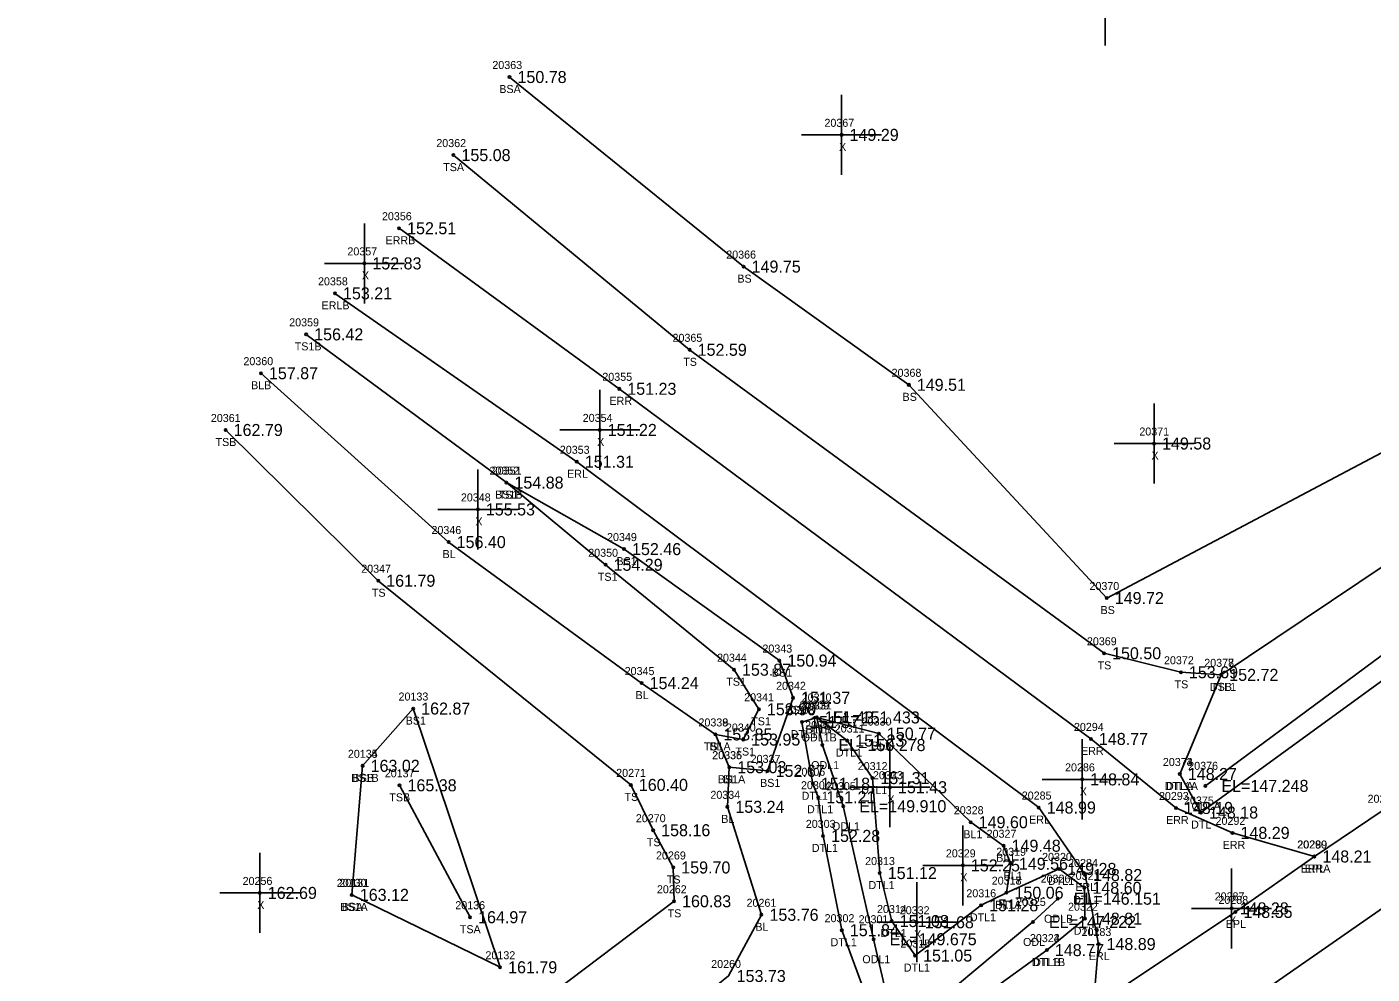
# Model space of a CAD drawing. Extents: x 2449605 to 2452431, y 1012876 to 1014922.
# Drawn here: x 2450467.1 to 2450635.2, y 1013641.9 to 1013760.1 of the extents above; entities that cross this region are included whole.
import ezdxf

# ---------------------------------------------------------------- set-up
doc = ezdxf.new("R2010")
doc.units = 0
for name, color, linetype in [('RD_DTM_BkLn1', 7, 'Continuous'), ('RD_DTM_BkLn2', 7, 'Continuous'), ('RD_DTM_BkLn_txCode', 7, 'Continuous'), ('RD_EX_H2O', 7, 'Continuous'), ('RD_EX_H2O_txCode', 7, 'Continuous'), ('RD_EX_Misc', 7, 'Continuous'), ('RD_EX_Misc_txCode', 7, 'Continuous'), ('RD_EX_Road', 7, 'Continuous'), ('RD_EX_Road_txCode', 7, 'Continuous'), ('RD_EX_TX_H2O_ELEV', 7, 'Continuous'), ('RD_EX_TX_Misc_ELEV', 7, 'Continuous'), ('RD_EX_TX_Road_ELEV', 7, 'Continuous'), ('RD_SMD_Locator', 7, 'Continuous')]:
    doc.layers.add(name, color=color, linetype=linetype)

msp = doc.modelspace()

# ---------------------------------------------------------------- linework, layer by layer
at = {"layer": 'RD_DTM_BkLn1'}
for points in [[(2449680.58, 1012985.87), (2449759.39, 1013040.31), (2449841.07, 1013097.15), (2449921.06, 1013152.87), (2450001.23, 1013208.89), (2450080.46, 1013264.17), (2450161.02, 1013320.22), (2450242.03, 1013376.29), (2450324.02, 1013432.88), (2450405.2, 1013489.3), (2450483.11, 1013543.86), (2450561.65, 1013598.14), (2450642.32, 1013654.18), (2450739.61, 1013721.61), (2450817.44, 1013775.86), (2450896.72, 1013831.42), (2450912.5, 1013842.34)], [(2450327.03, 1013465.64), (2450385.25, 1013515.48), (2450463.3, 1013570.54), (2450494.41, 1013598.14), (2450510.44, 1013608.45), (2450522.79, 1013616.8), (2450540.89, 1013630.45), (2450554.77, 1013641.65), (2450558.87, 1013649.29), (2450554.61, 1013662.77), (2450554.85, 1013667.72), (2450553.11, 1013671.81), (2450543.9, 1013678.22), (2450519.79, 1013695.83), (2450496.34, 1013716.91)], [(2450589.48, 1013652.05), (2450590.03, 1013655.66), (2450589.12, 1013657.91), (2450585.01, 1013660.85), (2450573.54, 1013671.92), (2450565.77, 1013673.93)]]:
    msp.add_lwpolyline(points, dxfattribs=at)
at = {"layer": 'RD_DTM_BkLn2'}
for p, q in [((2450507.69, 1013651.78), (2450509.04, 1013667.89)), ((2450522.47, 1013648.99), (2450513.65, 1013665.46))]:
    msp.add_line(p, q, dxfattribs=at)
for points in [[(2450527.39, 1013753.89), (2450556.64, 1013730.22), (2450577.28, 1013715.46), (2450602.01, 1013688.84), (2450690.63, 1013735.67), (2450719.37, 1013748.33)], [(2450520.39, 1013744.14), (2450549.9, 1013719.83), (2450601.67, 1013681.94), (2450611.27, 1013679.57), (2450616.31, 1013679.25)], [(2450553.11, 1013671.81), (2450556.59, 1013671.17), (2450558.55, 1013674.95), (2450555.44, 1013679.89), (2450539.39, 1013692.99), (2450527.01, 1013703.25), (2450501.99, 1013721.76)], [(2450301.63, 1013463.11), (2450375.81, 1013524.05), (2450456.92, 1013583.6), (2450494.97, 1013610.67), (2450491.89, 1013618.21), (2450482.67, 1013624.66), (2450481.76, 1013627.8), (2450488.9, 1013631.4), (2450492.06, 1013631.7), (2450504.7, 1013625.87), (2450511.15, 1013621.59), (2450516.87, 1013625.3), (2450533.14, 1013639.8), (2450547.95, 1013650.98), (2450547.85, 1013655.2), (2450545.34, 1013659.85), (2450542.55, 1013665.51), (2450510.99, 1013691), (2450491.93, 1013709.82)], [(2450554.85, 1013667.72), (2450559.64, 1013667.26), (2450562.82, 1013676.38), (2450561.11, 1013681.03), (2450541.7, 1013694.95), (2450527.01, 1013703.25)], [(2450507.69, 1013651.78), (2450526.22, 1013642.74), (2450515.36, 1013675.04), (2450509.04, 1013667.89)]]:
    msp.add_lwpolyline(points, dxfattribs=at)
at = {"layer": 'RD_EX_H2O'}
for points in [[(2450611.14, 1013666.87), (2450616.31, 1013679.25), (2450719.37, 1013748.33), (2450722.94, 1013749.68), (2450728.13, 1013757.45), (2450733.94, 1013756.08)], [(2450611.14, 1013666.87), (2450613.78, 1013662.06), (2450716.62, 1013736.81), (2450727.45, 1013740.5), (2450727.63, 1013739.78), (2450734.85, 1013745.44), (2450737.25, 1013753.64), (2450733.94, 1013756.08)], [(2450614.33, 1013665.39), (2450714.94, 1013739.79), (2450717.62, 1013740.69), (2450725.97, 1013743.31), (2450729.59, 1013752.89)], [(2450572.09, 1013638.8), (2450568.91, 1013647.37), (2450566.57, 1013659.14), (2450565.97, 1013663.97), (2450565.3, 1013665.65), (2450563.93, 1013673.35), (2450565.77, 1013673.93), (2450569.58, 1013671.05), (2450572.73, 1013666.36), (2450573.65, 1013654.5), (2450575.14, 1013648.51), (2450578.06, 1013644.2), (2450586.32, 1013650.48), (2450589.48, 1013652.05), (2450596.08, 1013655.02), (2450599.22, 1013652.66), (2450599.29, 1013648.8), (2450594.53, 1013644.88)], [(2450576.23, 1013634.6), (2450574.68, 1013638.41), (2450572.88, 1013646.24), (2450569.09, 1013662.85), (2450566.49, 1013670.48), (2450565.77, 1013673.93)], [(2450086.85, 1013301.88), (2450146.88, 1013340.5), (2450228.43, 1013395.92), (2450309.72, 1013451.69), (2450392.54, 1013506.78), (2450470.72, 1013561.36), (2450549.83, 1013616.71), (2450576.23, 1013634.6), (2450592.79, 1013648.4), (2450595.89, 1013651.3)], [(2450082.81, 1013302.86), (2450086.85, 1013297.03), (2450148.02, 1013337.87), (2450230.55, 1013392.65), (2450311.52, 1013448.88), (2450394.54, 1013504.43), (2450473.16, 1013557.42), (2450552.01, 1013612.78), (2450577.68, 1013632.73), (2450594.53, 1013644.88)]]:
    msp.add_lwpolyline(points, dxfattribs=at)
at = {"layer": 'RD_EX_Misc'}
for p, q in [((2450601.83, 1013757.82), (2450601.83, 1013767.82)), ((2450568.88, 1013741.67), (2450568.88, 1013751.67)), ((2450563.88, 1013746.67), (2450573.88, 1013746.67)), ((2450509.26, 1013725.62), (2450509.26, 1013735.62)), ((2450504.26, 1013730.62), (2450514.26, 1013730.62)), ((2450538.66, 1013704.83), (2450538.66, 1013714.83)), ((2450607.92, 1013703.13), (2450607.92, 1013713.13)), ((2450533.66, 1013709.83), (2450543.66, 1013709.83)), ((2450602.92, 1013708.13), (2450612.92, 1013708.13)), ((2450523.44, 1013694.9), (2450523.44, 1013704.9)), ((2450518.44, 1013699.9), (2450528.44, 1013699.9)), ((2450598.94, 1013661.2), (2450598.94, 1013671.2)), ((2450574.92, 1013660.22), (2450574.92, 1013670.22)), ((2450593.94, 1013666.2), (2450603.94, 1013666.2)), ((2450569.92, 1013665.22), (2450579.92, 1013665.22)), ((2450584.03, 1013650.46), (2450584.03, 1013660.46)), ((2450496.19, 1013647.02), (2450496.19, 1013657.02)), ((2450579.03, 1013655.46), (2450589.03, 1013655.46)), ((2450617.61, 1013645.09), (2450617.61, 1013655.09)), ((2450578.27, 1013643.36), (2450578.27, 1013653.36)), ((2450491.19, 1013652.02), (2450501.19, 1013652.02)), ((2450612.61, 1013650.09), (2450622.61, 1013650.09)), ((2450573.27, 1013648.36), (2450583.27, 1013648.36))]:
    msp.add_line(p, q, dxfattribs=at)
at = {"layer": 'RD_EX_Road'}
for points in [[(2449674.89, 1012994.69), (2449752.35, 1013048.28), (2449834.92, 1013105.96), (2449914.72, 1013161.11), (2449995.66, 1013217.59), (2450075.29, 1013272.9), (2450081.34, 1013277.24), (2450093.41, 1013285.64), (2450155.49, 1013328.69), (2450236.05, 1013384.7), (2450317.88, 1013441.24), (2450398.87, 1013497.28), (2450477.09, 1013551.76), (2450555.6, 1013606.73), (2450600.18, 1013637.7), (2450618.08, 1013649.65), (2450627.95, 1013656.57), (2450636.43, 1013662.28), (2450733.79, 1013730.39), (2450811.43, 1013784.18), (2450891.39, 1013839.9), (2450907.04, 1013850.14)], [(2450627.95, 1013656.57), (2450617.72, 1013659.52), (2450610.65, 1013662.63), (2450600.03, 1013671.25), (2450541.11, 1013714.96), (2450513.6, 1013735.01)], [(2450600.18, 1013637.7), (2450600.45, 1013639.09), (2450600.98, 1013645.64), (2450599.3, 1013654.26), (2450593.51, 1013662.68), (2450535.8, 1013705.85), (2450505.59, 1013726.88)]]:
    msp.add_lwpolyline(points, dxfattribs=at)
at = {"layer": 'RD_SMD_Locator'}
for centre in [(2450527.39, 1013753.89), (2450568.88, 1013746.67), (2450520.39, 1013744.14), (2450513.6, 1013735.01), (2450509.26, 1013730.62), (2450556.64, 1013730.22), (2450505.59, 1013726.88), (2450501.99, 1013721.76), (2450549.9, 1013719.83), (2450496.34, 1013716.91), (2450541.11, 1013714.96), (2450577.28, 1013715.46), (2450491.93, 1013709.82), (2450538.66, 1013709.83), (2450607.92, 1013708.13), (2450535.8, 1013705.85), (2450527.01, 1013703.25), (2450527.01, 1013703.25), (2450523.44, 1013699.9), (2450519.79, 1013695.83), (2450541.7, 1013694.95), (2450539.39, 1013692.99), (2450510.99, 1013691), (2450602.01, 1013688.84), (2450561.11, 1013681.03), (2450601.67, 1013681.94), (2450555.44, 1013679.89), (2450611.27, 1013679.57), (2450616.31, 1013679.25), (2450616.31, 1013679.25), (2450543.9, 1013678.22), (2450562.82, 1013676.38), (2450515.36, 1013675.04), (2450558.55, 1013674.95), (2450563.93, 1013673.35), (2450565.77, 1013673.93), (2450565.77, 1013673.93), (2450565.77, 1013673.93), (2450553.11, 1013671.81), (2450553.11, 1013671.81), (2450556.59, 1013671.17), (2450569.58, 1013671.05), (2450573.54, 1013671.92), (2450600.03, 1013671.25), (2450566.49, 1013670.48), (2450509.04, 1013667.89), (2450509.04, 1013667.89), (2450554.85, 1013667.72), (2450554.85, 1013667.72), (2450559.64, 1013667.26), (2450565.3, 1013665.65), (2450572.73, 1013666.36), (2450598.94, 1013666.2), (2450611.14, 1013666.87), (2450611.14, 1013666.87), (2450513.65, 1013665.46), (2450542.55, 1013665.51), (2450565.97, 1013663.97), (2450574.92, 1013665.22), (2450614.33, 1013665.39), (2450554.61, 1013662.77), (2450569.09, 1013662.85), (2450593.51, 1013662.68), (2450610.65, 1013662.63), (2450585.01, 1013660.85), (2450613.78, 1013662.06), (2450545.34, 1013659.85), (2450566.57, 1013659.14), (2450617.72, 1013659.52), (2450589.12, 1013657.91), (2450590.03, 1013655.66), (2450627.95, 1013656.57), (2450627.95, 1013656.57), (2450547.85, 1013655.2), (2450573.65, 1013654.5), (2450584.03, 1013655.46), (2450596.08, 1013655.02), (2450599.3, 1013654.26), (2450599.22, 1013652.66), (2450496.19, 1013652.02), (2450507.69, 1013651.78), (2450507.69, 1013651.78), (2450547.95, 1013650.98), (2450586.32, 1013650.48), (2450589.48, 1013652.05), (2450589.48, 1013652.05), (2450595.89, 1013651.3), (2450522.47, 1013648.99), (2450558.87, 1013649.29), (2450599.29, 1013648.8), (2450617.61, 1013650.09), (2450618.08, 1013649.65), (2450568.91, 1013647.37), (2450575.14, 1013648.51), (2450578.27, 1013648.36), (2450592.79, 1013648.4), (2450572.88, 1013646.24), (2450600.98, 1013645.64), (2450578.06, 1013644.2), (2450594.53, 1013644.88), (2450594.53, 1013644.88), (2450526.22, 1013642.74)]:
    msp.add_circle(centre, 0.15, dxfattribs=at)

# ---------------------------------------------------------------- texts
at = {"layer": 'RD_DTM_BkLn_txCode'}
for s, p in [('20363', (2450525.25, 1013754.89)), ('BSA', (2450526.12, 1013751.89)), ('20362', (2450518.25, 1013745.14)), ('TSA', (2450519.11, 1013742.14)), ('20366', (2450554.47, 1013731.22)), ('BS', (2450555.86, 1013728.22)), ('20359', (2450499.87, 1013722.76)), ('20365', (2450547.76, 1013720.83)), ('TS1B', (2450500.56, 1013719.76)), ('20360', (2450494.15, 1013717.91)), ('TS', (2450549.1, 1013717.83)), ('20368', (2450575.13, 1013716.46)), ('BLB', (2450495.11, 1013714.91)), ('BS', (2450576.5, 1013713.46)), ('20361', (2450490.08, 1013710.82)), ('TSB', (2450490.67, 1013707.82)), ('20352', (2450524.89, 1013704.25)), ('20351', (2450525.18, 1013704.25)), ('BS1B', (2450525.59, 1013701.25)), ('TS1', (2450526.05, 1013701.25)), ('20346', (2450517.64, 1013696.83)), ('20349', (2450539.58, 1013695.95)), ('BL', (2450519.03, 1013693.83)), ('20350', (2450537.23, 1013693.99)), ('20347', (2450508.87, 1013692)), ('BS1', (2450540.75, 1013692.95)), ('TS1', (2450538.43, 1013690.99)), ('TS', (2450510.2, 1013689)), ('20370', (2450599.85, 1013689.84)), ('BS', (2450601.23, 1013686.84)), ('20343', (2450558.99, 1013682.03)), ('20369', (2450599.53, 1013682.94)), ('20344', (2450553.32, 1013680.89)), ('TS', (2450600.87, 1013679.94)), ('20372', (2450609.16, 1013680.57)), ('20378', (2450614.19, 1013680.25)), ('20345', (2450541.78, 1013679.22)), ('BS1', (2450560.17, 1013679.03)), ('TS1', (2450554.48, 1013677.89)), ('20342', (2450560.7, 1013677.38)), ('TS', (2450610.48, 1013677.57)), ('TSB', (2450615.04, 1013677.25)), ('20133', (2450513.53, 1013676.04)), ('BL', (2450543.14, 1013676.22)), ('20341', (2450556.71, 1013675.95)), ('20331', (2450563.94, 1013674.93)), ('BS1', (2450561.87, 1013674.38)), ('BS1', (2450514.42, 1013673.04)), ('20338', (2450551, 1013672.81)), ('20339', (2450551, 1013672.81)), ('20340', (2450554.43, 1013672.17)), ('TS1', (2450557.59, 1013672.95)), ('BL1B', (2450564.38, 1013671.93)), ('20330', (2450571.39, 1013672.92)), ('TS1A', (2450551.67, 1013669.81)), ('BL', (2450552.36, 1013669.81)), ('BL1', (2450572.62, 1013669.92)), ('20134', (2450507.2, 1013668.89)), ('20135', (2450507.2, 1013668.89)), ('20336', (2450552.71, 1013668.72)), ('20335', (2450552.73, 1013668.72)), ('TS1', (2450555.62, 1013669.17)), ('20337', (2450557.52, 1013668.26)), ('20137', (2450511.81, 1013666.46)), ('20271', (2450540.72, 1013666.51)), ('BS1B', (2450507.62, 1013665.89)), ('BSB', (2450507.78, 1013665.89)), ('BS1A', (2450553.42, 1013665.72)), ('BL', (2450554.09, 1013665.72)), ('BS1', (2450558.7, 1013665.26)), ('TSB', (2450512.38, 1013663.46)), ('TS', (2450541.76, 1013663.51)), ('20334', (2450552.49, 1013663.77)), ('20328', (2450582.9, 1013661.85)), ('20270', (2450543.18, 1013660.85)), ('BL', (2450553.85, 1013660.77)), ('BL1', (2450584.09, 1013658.85)), ('20327', (2450587, 1013658.91)), ('TS', (2450544.55, 1013657.85)), ('20319', (2450588.2, 1013656.66)), ('20269', (2450545.7, 1013656.2)), ('BL1', (2450588.2, 1013655.91)), ('TS', (2450547.05, 1013653.2)), ('20318', (2450587.64, 1013653.05)), ('BL1', (2450589.11, 1013653.66)), ('20130', (2450505.81, 1013652.78)), ('20131', (2450506.14, 1013652.78)), ('20262', (2450545.81, 1013651.98)), ('BS1A', (2450506.25, 1013649.78)), ('BSA', (2450506.42, 1013649.78)), ('20136', (2450520.62, 1013649.99)), ('20261', (2450557.01, 1013650.29)), ('BL1A', (2450588.07, 1013650.05)), ('TS', (2450547.15, 1013648.98)), ('TSA', (2450521.19, 1013646.99)), ('BL', (2450558.11, 1013647.29)), ('20132', (2450524.39, 1013643.74)), ('20260', (2450552.59, 1013642.65))]:
    msp.add_text(s, height=1, dxfattribs=at).set_placement(p)
at = {"layer": 'RD_EX_H2O_txCode'}
for s, p in [('20377', (2450614.19, 1013680.25)), ('DTL1', (2450614.9, 1013677.25)), ('20309', (2450563.61, 1013674.93)), ('20310', (2450563.9, 1013675.93)), ('20308', (2450561.77, 1013674.35)), ('20307', (2450564.33, 1013672.48)), ('DTL1', (2450564.36, 1013671.93)), ('20311', (2450568.03, 1013672.05)), ('DTL1', (2450562.52, 1013671.35)), ('ODL1B', (2450563.89, 1013670.93)), ('DTL1', (2450568.17, 1013669.05)), ('20306', (2450563.12, 1013666.65)), ('ODL1', (2450565.08, 1013667.48)), ('20312', (2450570.9, 1013667.36)), ('20373', (2450609.02, 1013667.87)), ('20374', (2450609.02, 1013667.87)), ('20376', (2450612.19, 1013667.39)), ('20304', (2450563.81, 1013664.97)), ('20305', (2450566.93, 1013664.85)), ('DTL1A', (2450609.24, 1013664.87)), ('DTLA', (2450609.41, 1013664.87)), ('DTL1', (2450563.89, 1013663.65)), ('DTL1', (2450571.32, 1013664.36)), ('20375', (2450611.66, 1013663.06)), ('DTL1', (2450564.56, 1013661.97)), ('ODLA', (2450612.6, 1013662.39)), ('20303', (2450564.41, 1013660.14)), ('ODL1', (2450567.68, 1013659.85)), ('DTL', (2450612.54, 1013660.06)), ('DTL1', (2450565.16, 1013657.14)), ('20313', (2450571.82, 1013655.5)), ('20320', (2450593.93, 1013656.02)), ('20317', (2450587.64, 1013653.05)), ('20326', (2450593.75, 1013653.3)), ('DTL1', (2450594.67, 1013653.02)), ('20321', (2450597.38, 1013653.66)), ('DTL1', (2450572.24, 1013652.5)), ('20316', (2450584.47, 1013651.48)), ('DTL1', (2450588.07, 1013650.05)), ('20325', (2450590.67, 1013650.4)), ('20322', (2450597.17, 1013649.8)), ('DTL1', (2450597.81, 1013650.66)), ('20302', (2450566.76, 1013648.37)), ('20301', (2450571.01, 1013648.24)), ('20314', (2450573.31, 1013649.51)), ('DTL1', (2450584.91, 1013648.48)), ('ODLB', (2450594.17, 1013648.3)), ('DTL1', (2450573.73, 1013646.51)), ('DTL1', (2450597.88, 1013646.8)), ('DTL1', (2450567.51, 1013645.37)), ('20315', (2450576.23, 1013645.2)), ('ODL', (2450591.55, 1013645.4)), ('20323', (2450592.41, 1013645.88)), ('20324', (2450592.41, 1013645.88)), ('ODL1', (2450571.47, 1013643.24)), ('DTL1', (2450576.65, 1013642.2)), ('DTL1B', (2450592.65, 1013642.88)), ('DTLB', (2450592.81, 1013642.88))]:
    msp.add_text(s, height=1, dxfattribs=at).set_placement(p)
at = {"layer": 'RD_EX_Misc_txCode'}
for s, p in [('20367', (2450566.74, 1013747.67)), ('X', (2450568.57, 1013744.67)), ('20357', (2450507.14, 1013731.62)), ('X', (2450508.95, 1013728.62)), ('20354', (2450536.54, 1013710.83)), ('20371', (2450606.08, 1013709.13)), ('X', (2450538.34, 1013707.83)), ('X', (2450607.6, 1013706.13)), ('20348', (2450521.32, 1013700.9)), ('X', (2450523.13, 1013697.9)), ('20286', (2450596.8, 1013667.2)), ('20333', (2450572.8, 1013666.22)), ('X', (2450574.61, 1013663.22)), ('X', (2450598.63, 1013664.2)), ('20329', (2450581.91, 1013656.46)), ('20256', (2450494.05, 1013653.02)), ('X', (2450583.71, 1013653.46)), ('X', (2450495.88, 1013650.02)), ('20287', (2450615.49, 1013651.09)), ('20332', (2450576.15, 1013649.36)), ('X', (2450617.29, 1013648.09)), ('X', (2450577.95, 1013646.36))]:
    msp.add_text(s, height=1, dxfattribs=at).set_placement(p)
at = {"layer": 'RD_EX_Road_txCode'}
for s, p in [('20356', (2450511.46, 1013736.01)), ('ERRB', (2450511.9, 1013733.01)), ('20358', (2450503.47, 1013727.88)), ('ERLB', (2450503.91, 1013724.88)), ('20355', (2450538.99, 1013715.96)), ('ERR', (2450539.88, 1013712.96)), ('20353', (2450533.68, 1013706.85)), ('ERL', (2450534.59, 1013703.85)), ('20294', (2450597.91, 1013672.25)), ('ERR', (2450598.8, 1013669.25)), ('20285', (2450591.39, 1013663.68)), ('20293', (2450608.53, 1013663.63)), ('20291', (2450634.59, 1013663.28)), ('ERL', (2450592.31, 1013660.68)), ('ERR', (2450609.42, 1013660.63)), ('20292', (2450615.6, 1013660.52)), ('ERR', (2450616.49, 1013657.52)), ('20290', (2450625.79, 1013657.57)), ('20289', (2450625.83, 1013657.57)), ('20284', (2450597.18, 1013655.26)), ('ERRA', (2450626.23, 1013654.57)), ('EPL', (2450626.74, 1013654.57)), ('ERL', (2450598.09, 1013652.26)), ('20288', (2450615.96, 1013650.65)), ('20283', (2450598.86, 1013646.64)), ('EPL', (2450616.88, 1013647.65)), ('ERL', (2450599.77, 1013643.64))]:
    msp.add_text(s, height=1, dxfattribs=at).set_placement(p)
at = {"layer": 'RD_EX_TX_H2O_ELEV'}
for s, p in [('152.72', (2450617.31, 1013678.5)), ('151.43', (2450566.77, 1013673.18)), ('EL=151.433', (2450567.77, 1013673.18)), ('151.57', (2450564.93, 1013672.6)), ('EL=150.278', (2450568.49, 1013669.73)), ('151.23', (2450570.58, 1013670.3)), ('148.27', (2450612.14, 1013666.12)), ('148.27', (2450612.14, 1013666.12)), ('151.18', (2450566.3, 1013664.9)), ('151.31', (2450573.73, 1013665.61)), ('EL=147.248', (2450616.33, 1013664.64)), ('151.21', (2450566.97, 1013663.22)), ('EL=149.910', (2450571.09, 1013662.1)), ('148.18', (2450614.78, 1013661.31)), ('152.28', (2450567.57, 1013658.39)), ('149.28', (2450597.08, 1013654.27)), ('151.12', (2450574.65, 1013653.75)), ('150.06', (2450590.48, 1013651.3)), ('148.60', (2450600.22, 1013651.91)), ('151.28', (2450587.32, 1013649.73)), ('EL=146.151', (2450597.89, 1013650.55)), ('151.08', (2450576.14, 1013647.76)), ('EL=147.222', (2450594.79, 1013647.65)), ('148.81', (2450600.29, 1013648.05)), ('151.84', (2450569.91, 1013646.62)), ('EL=149.675', (2450574.88, 1013645.49)), ('148.77', (2450595.53, 1013644.13)), ('148.77', (2450595.53, 1013644.13)), ('151.05', (2450579.06, 1013643.45))]:
    msp.add_text(s, height=1.5, dxfattribs=at).set_placement(p)
at = {"layer": 'RD_EX_TX_Misc_ELEV'}
for s, p in [('150.78', (2450528.39, 1013753.14)), ('149.29', (2450569.88, 1013745.92)), ('155.08', (2450521.39, 1013743.39)), ('152.83', (2450510.26, 1013729.87)), ('149.75', (2450557.64, 1013729.47)), ('156.42', (2450502.99, 1013721.01)), ('152.59', (2450550.9, 1013719.08)), ('157.87', (2450497.34, 1013716.16)), ('149.51', (2450578.28, 1013714.71)), ('162.79', (2450492.93, 1013709.07)), ('151.22', (2450539.66, 1013709.08)), ('149.58', (2450608.92, 1013707.38)), ('154.88', (2450528.01, 1013702.5)), ('154.88', (2450528.01, 1013702.5)), ('155.53', (2450524.44, 1013699.15)), ('156.40', (2450520.79, 1013695.08)), ('152.46', (2450542.7, 1013694.2)), ('154.29', (2450540.39, 1013692.24)), ('161.79', (2450511.99, 1013690.25)), ('149.72', (2450603.01, 1013688.09)), ('150.50', (2450602.67, 1013681.19)), ('150.94', (2450562.11, 1013680.28)), ('153.87', (2450556.44, 1013679.14)), ('153.69', (2450612.27, 1013678.82)), ('152.72', (2450617.31, 1013678.5)), ('154.24', (2450544.9, 1013677.47)), ('151.37', (2450563.82, 1013675.63)), ('162.87', (2450516.36, 1013674.29)), ('153.90', (2450559.55, 1013674.2)), ('151.43', (2450566.77, 1013673.18)), ('153.85', (2450554.11, 1013671.06)), ('153.85', (2450554.11, 1013671.06)), ('150.77', (2450574.54, 1013671.17)), ('153.95', (2450557.59, 1013670.42)), ('163.02', (2450510.04, 1013667.14)), ('163.02', (2450510.04, 1013667.14)), ('153.03', (2450555.85, 1013666.97)), ('153.03', (2450555.85, 1013666.97)), ('152.67', (2450560.64, 1013666.51)), ('165.38', (2450514.65, 1013664.71)), ('160.40', (2450543.55, 1013664.76)), ('151.43', (2450575.92, 1013664.47)), ('148.84', (2450599.94, 1013665.45)), ('153.24', (2450555.61, 1013662.02)), ('149.60', (2450586.01, 1013660.1)), ('158.16', (2450546.34, 1013659.1)), ('149.48', (2450590.12, 1013657.16)), ('159.70', (2450548.85, 1013654.45)), ('152.25', (2450585.03, 1013654.71)), ('149.56', (2450591.03, 1013654.91)), ('162.69', (2450497.19, 1013651.27)), ('163.12', (2450508.69, 1013651.03)), ('163.12', (2450508.69, 1013651.03)), ('150.06', (2450590.48, 1013651.3)), ('160.83', (2450548.95, 1013650.23)), ('148.28', (2450618.61, 1013649.34)), ('164.97', (2450523.47, 1013648.24)), ('153.76', (2450559.87, 1013648.54)), ('151.68', (2450579.27, 1013647.61)), ('161.79', (2450527.22, 1013641.99)), ('153.73', (2450555.77, 1013640.9))]:
    msp.add_text(s, height=1.5, dxfattribs=at).set_placement(p)
at = {"layer": 'RD_EX_TX_Road_ELEV'}
for s, p in [('152.51', (2450514.6, 1013734.26)), ('153.21', (2450506.59, 1013726.13)), ('151.23', (2450542.11, 1013714.21)), ('151.31', (2450536.8, 1013705.1)), ('148.77', (2450601.03, 1013670.5)), ('148.99', (2450594.51, 1013661.93)), ('148.19', (2450611.65, 1013661.88)), ('148.29', (2450618.72, 1013658.77)), ('148.21', (2450628.95, 1013655.82)), ('148.21', (2450628.95, 1013655.82)), ('148.82', (2450600.3, 1013653.51)), ('148.55', (2450619.08, 1013648.9)), ('148.89', (2450601.98, 1013644.89))]:
    msp.add_text(s, height=1.5, dxfattribs=at).set_placement(p)

doc.saveas('drawing.dxf')
